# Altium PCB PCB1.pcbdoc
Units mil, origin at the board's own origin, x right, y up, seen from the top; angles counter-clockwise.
Board outline 4950 x 4950 mil, 2 copper layers (Top Layer, Bottom Layer); 35 components, 39 nets, 176 pads, 65 vias.
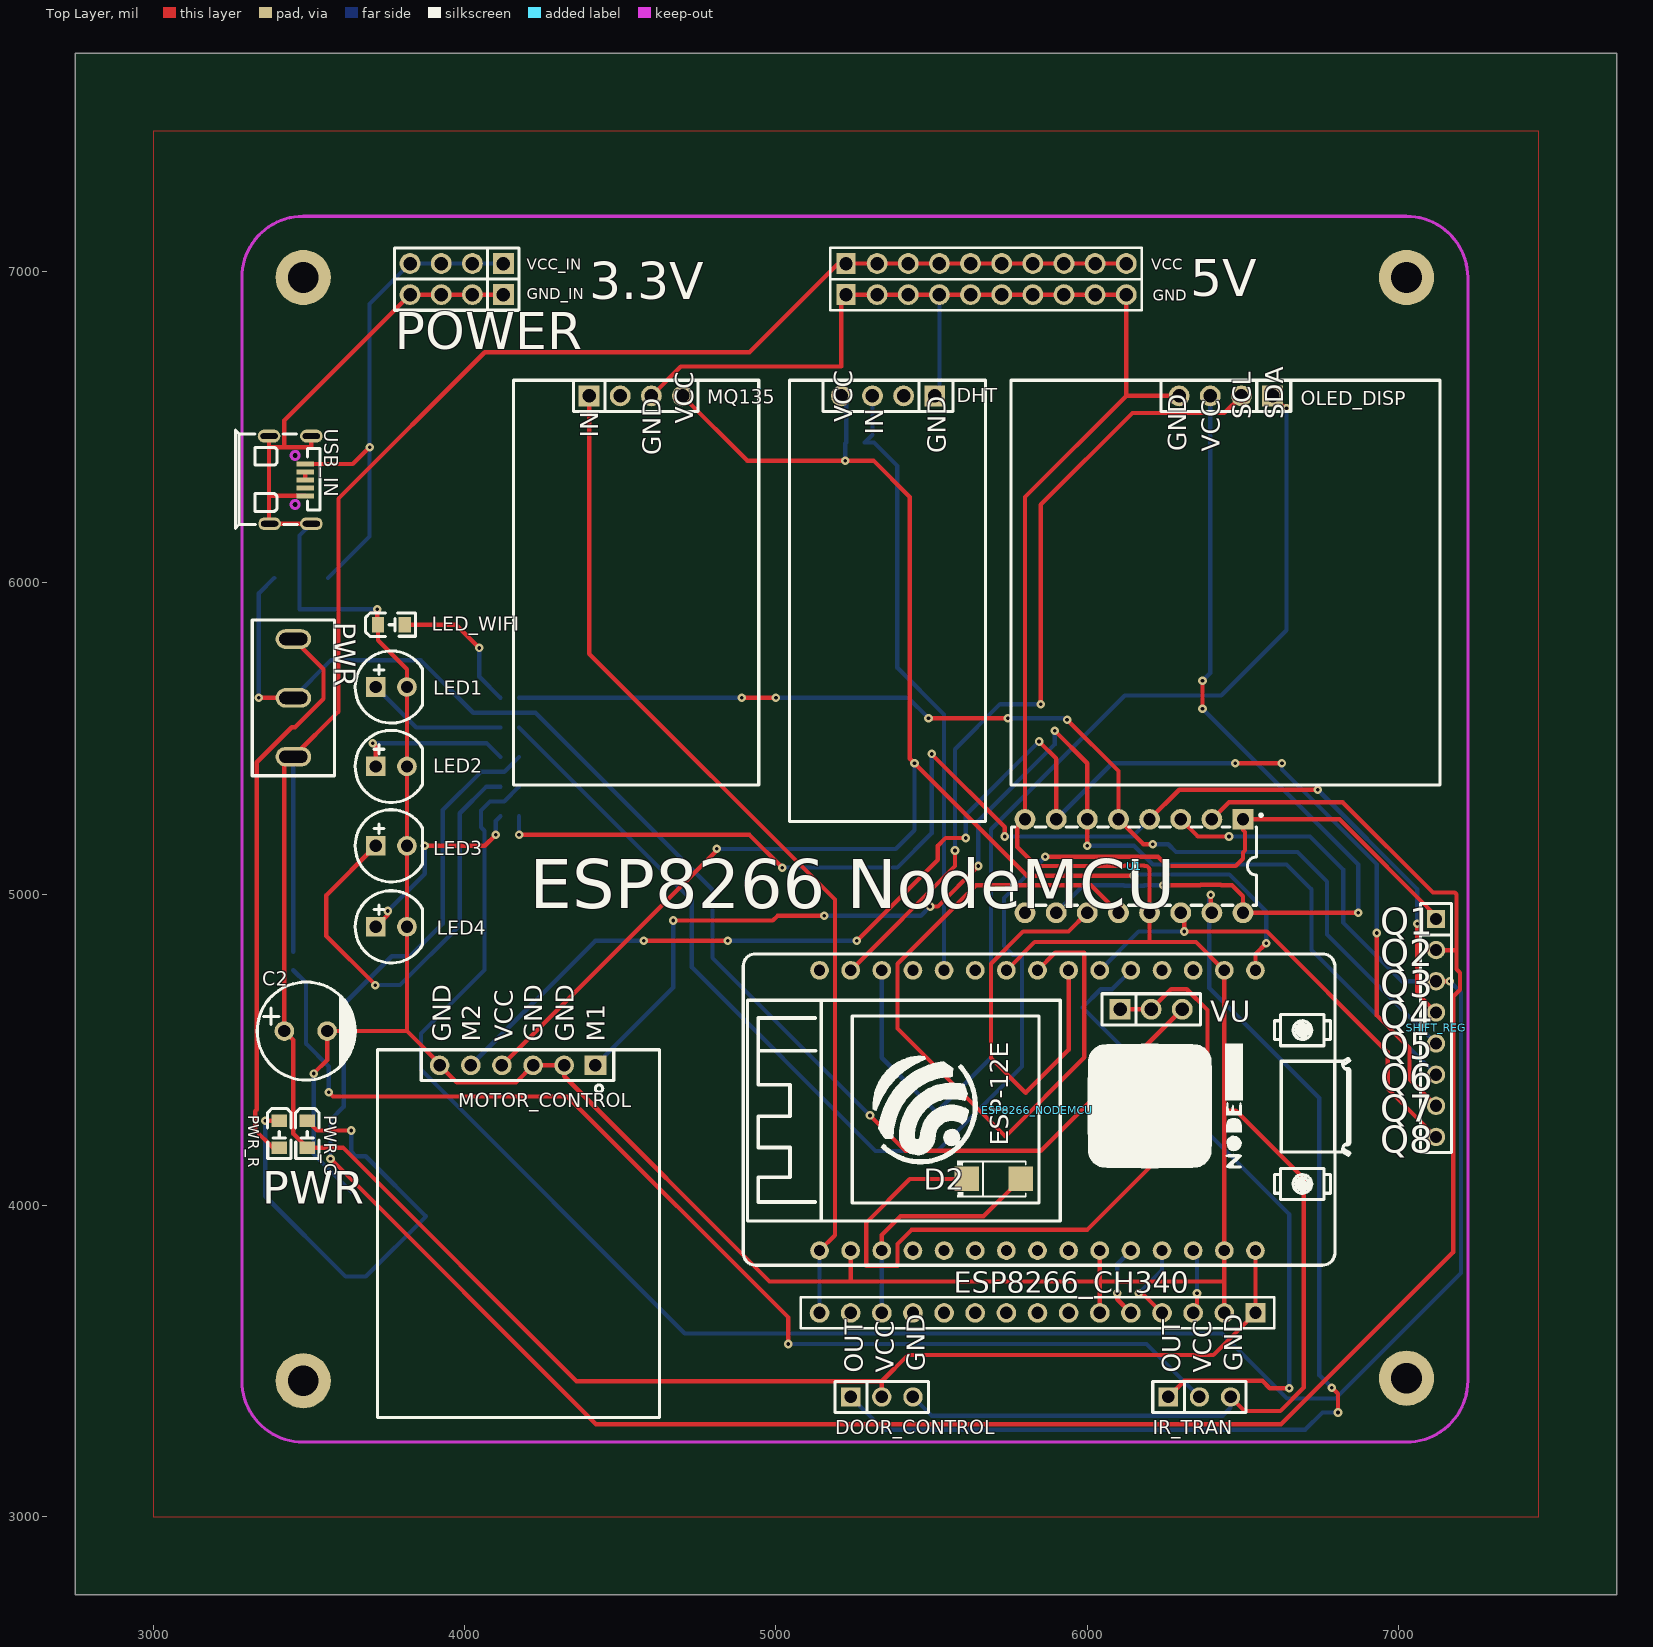
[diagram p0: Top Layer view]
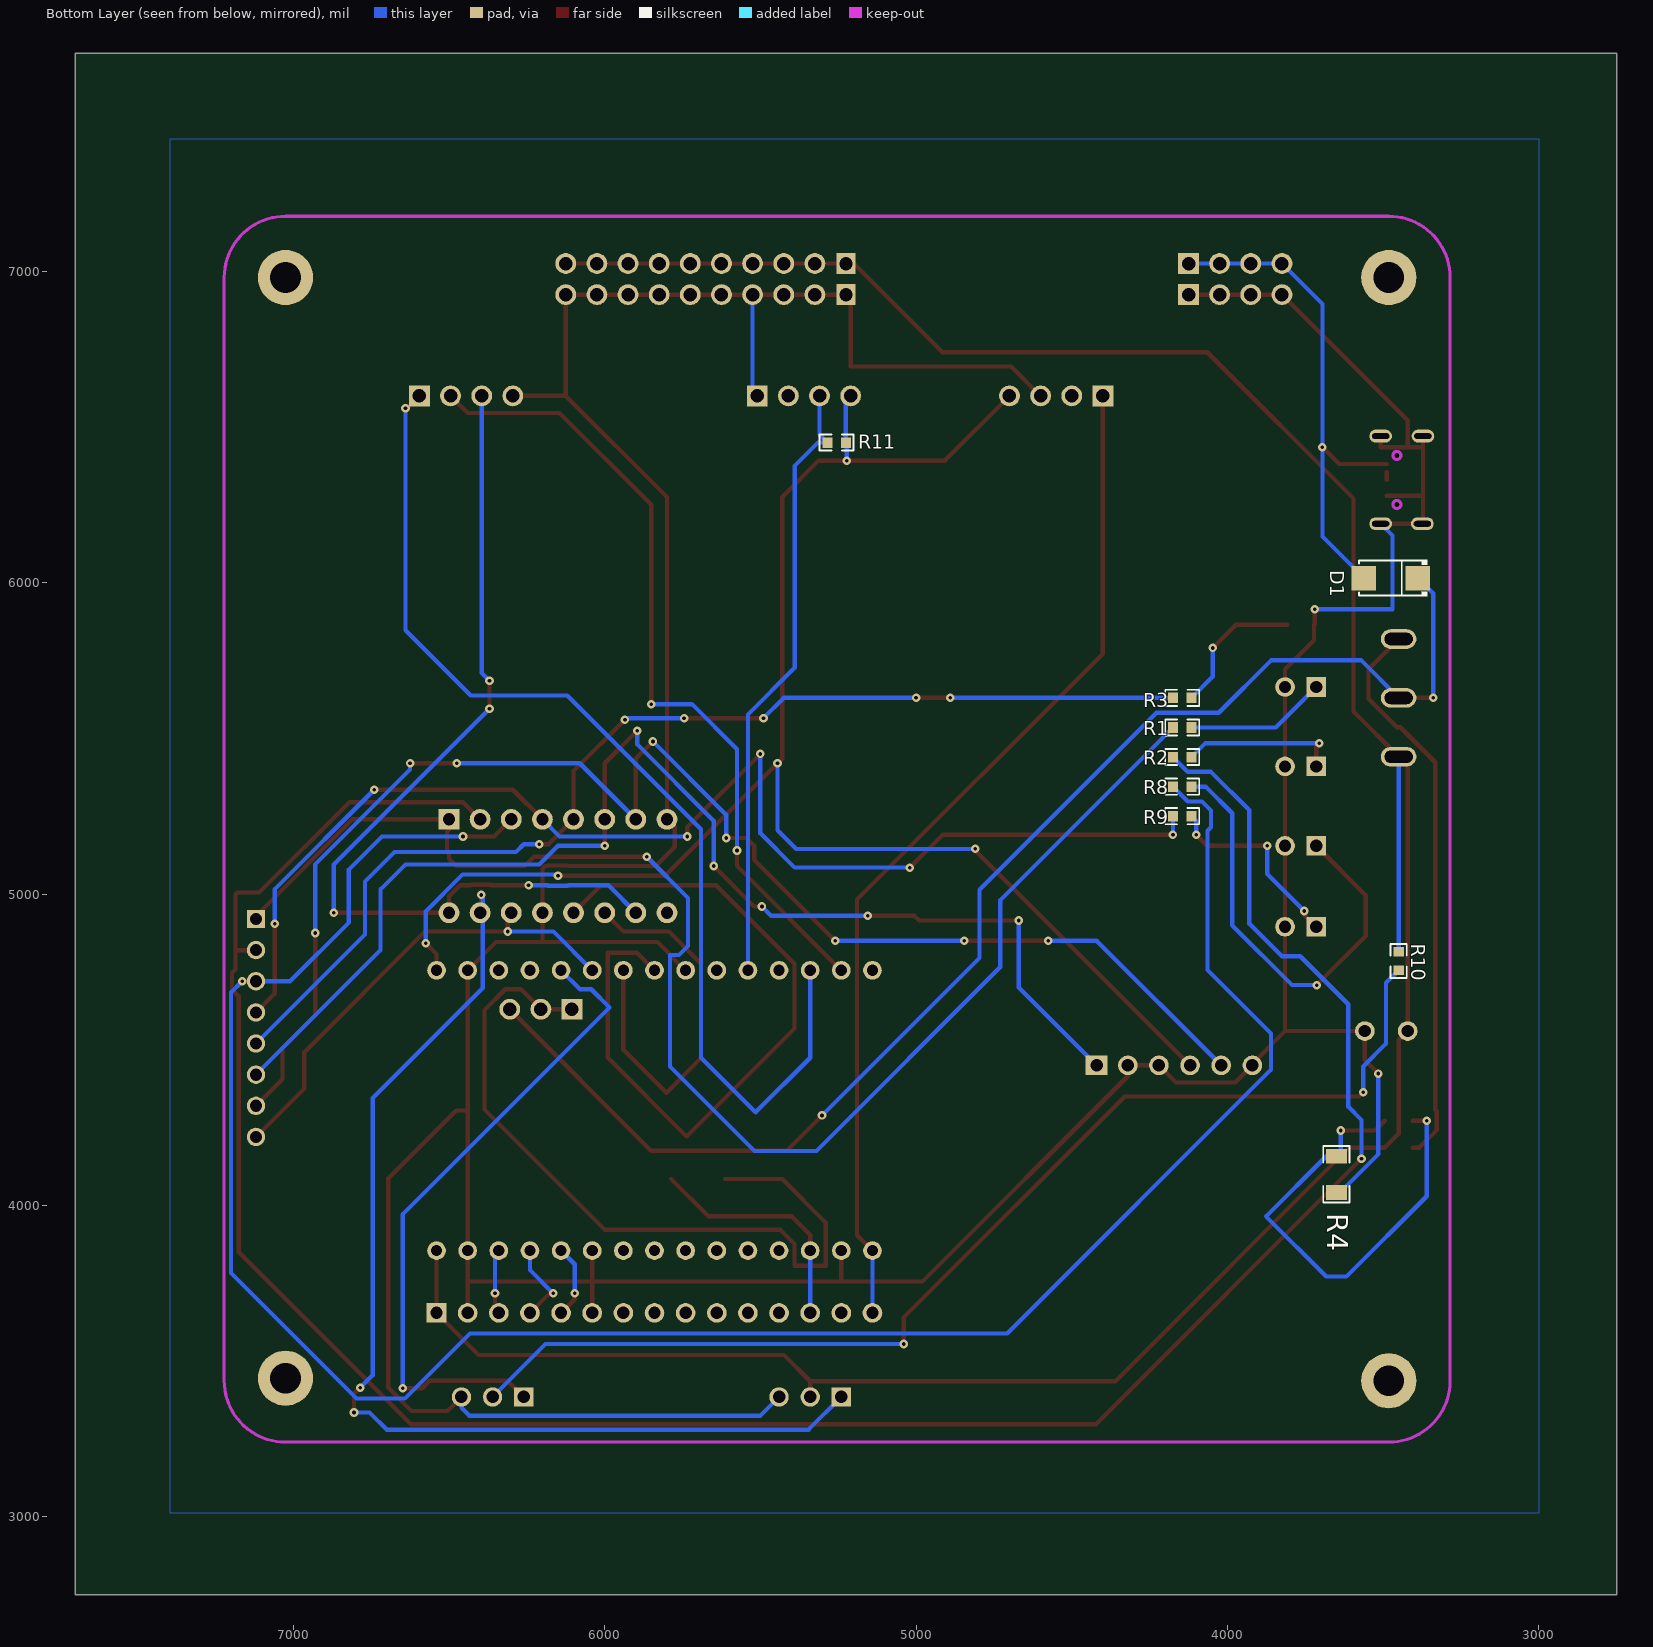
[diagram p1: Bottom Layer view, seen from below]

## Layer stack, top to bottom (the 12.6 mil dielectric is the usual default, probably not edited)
Top Layer: signal copper (thickness not stored)
Dielectric: dielectric 12.6, FR-4, Dk 4.8
Bottom Layer: signal copper (thickness not stored)

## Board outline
7700,2750 2750,2750 2750,7700 7700,7700

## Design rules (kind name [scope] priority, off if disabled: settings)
Clearance Default [All] p1: gap=7 ignorepadtopadclearanceinfootprint=FALSE except(0: Region-Region Region-Text Text-Text; 6: Track-Track Track-SMDPad SMDPad-SMDPad Track-THPad SMDPad-THPad THPad-THPad Track-Via SMDPad-Via THPad-Via Via-Via Track-Fill SMDPad-Fill THPad-Fill Via-Fill Fill-Fill Track-Region SMDPad-Region THPad-Region Via-Region Fill-Region Track-Poly SMDPad-Poly THPad-Poly Via-Poly Fill-Poly Region-Poly Poly-Poly Track-Text SMDPad-Text THPad-Text Via-Text Fill-Text Poly-Text Track-Sheet SMDPad-Sheet THPad-Sheet Via-Sheet Fill-Sheet Region-Sheet Poly-Sheet Text-Sheet Track-Hole SMDPad-Hole THPad-Hole Via-Hole Fill-Hole Region-Hole Poly-Hole Text-Hole Sheet-Hole)
Clearance Power [All] p1: gap=7 ignorepadtopadclearanceinfootprint=FALSE except(0: Region-Region Region-Text Text-Text; 6: Track-Sheet SMDPad-Sheet THPad-Sheet Via-Sheet Fill-Sheet Region-Sheet Poly-Sheet Text-Sheet Sheet-Hole; 6.3: Track-Track Track-SMDPad SMDPad-SMDPad Track-THPad SMDPad-THPad THPad-THPad Track-Via SMDPad-Via THPad-Via Via-Via Track-Fill SMDPad-Fill THPad-Fill Via-Fill Fill-Fill Track-Region SMDPad-Region THPad-Region Via-Region Fill-Region Track-Poly SMDPad-Poly THPad-Poly Via-Poly Fill-Poly Region-Poly Poly-Poly Track-Text SMDPad-Text THPad-Text Via-Text Fill-Text Poly-Text Track-Hole SMDPad-Hole THPad-Hole Via-Hole Fill-Hole Region-Hole Poly-Hole Text-Hole)
Clearance Wide [All] p1: gap=7 ignorepadtopadclearanceinfootprint=FALSE except(0: Region-Region Region-Text Text-Text; 6: Track-Sheet SMDPad-Sheet THPad-Sheet Via-Sheet Fill-Sheet Region-Sheet Poly-Sheet Text-Sheet Sheet-Hole; 7.1: Track-Track Track-SMDPad SMDPad-SMDPad Track-THPad SMDPad-THPad THPad-THPad Track-Via SMDPad-Via THPad-Via Via-Via Track-Fill SMDPad-Fill THPad-Fill Via-Fill Fill-Fill Track-Region SMDPad-Region THPad-Region Via-Region Fill-Region Track-Poly SMDPad-Poly THPad-Poly Via-Poly Fill-Poly Region-Poly Poly-Poly Track-Text SMDPad-Text THPad-Text Via-Text Fill-Text Poly-Text Track-Hole SMDPad-Hole THPad-Hole Via-Hole Fill-Hole Region-Hole Poly-Hole Text-Hole)
DiffPairsRouting differentialPair [All] p1: maxuncoupledlength=10 minlimit=6 maxlimit=50 mostfreqgap=6 toplayer_minwidth=5 toplayer_prefwidth=10 toplayer_maxwidth=100 bottomlayer_minwidth=5 bottomlayer_prefwidth=10 bottomlayer_maxwidth=100
PasteMaskExpansion Common [All] p1:
PlaneConnect Default [All] p1: planeconnectstyle=Relief reliefexpansion=20 reliefentries=4 reliefconductorwidth=0 reliefairgap=10
PlaneConnect Power [All] p1: planeconnectstyle=Relief reliefexpansion=20 reliefentries=4 reliefconductorwidth=0 reliefairgap=10
PlaneConnect Wide [All] p1: planeconnectstyle=Relief reliefexpansion=20 reliefentries=4 reliefconductorwidth=0 reliefairgap=10
PolygonConnect gge880165 [All] p1: connectstyle=Relief reliefentries=4 polygonreliefangle="90 Angle" airgapwidth=10
PolygonConnect gge880153 [All] p1: connectstyle=Relief reliefentries=4 polygonreliefangle="90 Angle" airgapwidth=10
RoutingVias Default [All] p1: viastyle="Through Hole" holewidth=11.8 minholewidth=11.8 maxholewidth=2362 width=27.6 minwidth=27.6 maxwidth=3938
RoutingVias Power [All] p1: viastyle="Through Hole" holewidth=11.8 minholewidth=11.8 maxholewidth=2362 width=27.6 minwidth=27.6 maxwidth=3938
RoutingVias Wide [All] p1: viastyle="Through Hole" holewidth=11.8 minholewidth=11.8 maxholewidth=2362 width=47.2 minwidth=47.2 maxwidth=3938
SolderMaskExpansion Common [All] p1: useseparateexpansions=TRUE expansion=2 expansionbottom=2
Width Default [All] p1: maxlimit=1000 minlimit=14 preferedwidth=14
Width Power [All] p1: maxlimit=1000 minlimit=20 preferedwidth=20
Width Wide [All] p1: maxlimit=1000 minlimit=39 preferedwidth=39

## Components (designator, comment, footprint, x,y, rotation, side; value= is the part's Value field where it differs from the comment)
C2 "1000uF" CAP-TH_BD8.0-P3.50-D0.6-FD 3490,4560 r0 top
D1 "SS34-A" SMA_L4.3-W2.6-LS5.2-RD 3475,6015 r0 bottom
D2 "SS34-A" SMA_L4.3-W2.6-LS5.2-RD 5700,4085 r0 top
DHT "HDR-F_2.54_1x4P" HDR-TH_4P-P2.54-V-F 5360,6600 r180 top
DOOR_CONTROL "HDR-F_2.54_1x3P" HDR-TH_3P-P2.54-V-F 5340,3385 r0 top
ESP8266_CH340 "HDR-F_2.54_1x15P" HDR-TH_15P-P2.54-V-F-1 5840,3655 r180 top
ESP8266_NODEMCU "NodeMCU8266" NODEMCU8266 6540,3855 r90 top
GND "HDR-M_2.54_1x10P" HDR-TH_10P-P2.54-V-M-1 5675,6925 r0 top
GND_IN "HDR-M_2.54_1x4P" HDR-TH_4P-P2.54-V-M 3975,6925 r180 top
IR_TRAN "HDR-F_2.54_1x3P" HDR-TH_3P-P2.54-V-F 6360,3385 r0 top
LED1 "LTST-C171KFKT" LED-TH_BD5.8-P2.54-RD 3765,5665 r0 top
LED2 "LTST-C171KFKT" LED-TH_BD5.8-P2.54-RD 3765,5410 r0 top
LED3 "LTST-C171KFKT" LED-TH_BD5.8-P2.54-RD 3765,5155 r0 top
LED4 "LTST-C171KFKT" LED-TH_BD5.8-P2.54-RD 3765,4895 r0 top
LED_WIFI "LTST-C171KFKT" LED0805-RD_ORANGE 3765,5865 r0 top
MOTOR_CONTROL "HDR-F_2.54_1x6P" HDR-TH_6P-P2.54-V-F 4170,4450 r180 top
MQ135 "HDR-M_2.54_1x4P" HDR-TH_4P-P2.54-V-M 4550,6600 r0 top
OLED_DISP "HDR-F_2.54_1x4P" HDR-TH_4P-P2.54-V-F 6445,6600 r180 top
PWR "SS12D10G5" SS12D10G5 3450,5630 r270 top
PWR_G "LTST-C170GKT" LED0805-RD_GREEN 3495,4228.94 r270 top
PWR_R "HL-PSC-2012S9AC-CZ" LED0805-RD_RED 3405,4228.94 r270 top
R1 "Res_0603" R0603 4145,5535 r180 bottom
R2 "Res_0603" R0603 4145,5440 r180 bottom
R3 "Res_0603" R0603 4145,5630 r180 bottom
R4 "10K" R1206 3650,4100 r90 bottom
R8 "Res_0603" R0603 4145,5345 r180 bottom
R9 "Res_0603" R0603 4145,5250 r180 bottom
R10 "Res_0603" R0603 3450,4785 r270 bottom
R11 "Res_0603" R0603 5255,6450 r0 bottom
SHIFT_REG "HDR-M_2.54_1x8P" HDR-TH_8P-P2.54-V-M 7120,4570 r270 top
U1 "74HC595D,118" CDIP-16_L19.7-W6.6-P2.54-LS7.6-BL 6150,5090 r180 top
USB_IN "MICROUSB_5PIN_4DIP" MICRO-USB-SMD_U254-051N-4BH806 3440,6330 r270 top
VCC "HDR-M_2.54_1x10P" HDR-TH_10P-P2.54-V-M-1 5675,7025 r0 top
VCC_IN "HDR-M_2.54_1x4P" HDR-TH_4P-P2.54-V-M 3975,7025 r180 top
VU "HDR-M_2.54_1x3P" HDR-TH_3P-P2.54-V-M 6205,4630 r0 top

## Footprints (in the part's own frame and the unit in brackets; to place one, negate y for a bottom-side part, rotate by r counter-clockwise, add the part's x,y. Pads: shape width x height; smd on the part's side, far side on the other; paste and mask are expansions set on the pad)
CAP-TH_BD8.0-P3.50-D0.6-FD [mm]
  round 1.6 hole 1: 1(-1.75,0) 2(1.75,0)
  silkscreen extent -3.96,-4 4.04,4
CDIP-16_L19.7-W6.6-P2.54-LS7.6-BL [mm]
  rect 1.7x1.7 hole 1: 1(-8.89,-3.81)
  round 1.7 hole 1: 2(-6.35,-3.81) 3(-3.81,-3.81) 4(-1.27,-3.81) 5(1.27,-3.81) 6(3.81,-3.81) 7(6.35,-3.81) 8(8.89,-3.81) 9(8.89,3.81) 10(6.35,3.81) 11(3.81,3.81) 12(1.27,3.81) 13(-1.27,3.81) 14(-3.81,3.81) 15(-6.35,3.81) 16(-8.89,3.81)
  silkscreen extent -10.46,-4.26 10,3.2
HDR-TH_3P-P2.54-V-F [mil]
  rect 62x62 hole 40.16: 1(-100,0)
  round 62 hole 40.16: 2(0,0) 3(100,0)
  silkscreen extent -150,-50 150,50
HDR-TH_3P-P2.54-V-M [mm]
  rect 1.7x1.7 hole 1.1: 1(-2.54,0)
  round 1.7 hole 1.1: 2(0,0) 3(2.54,0)
  silkscreen extent -4.02,-1.27 4.02,1.27
HDR-TH_4P-P2.54-V-F [mm]
  rect 1.7x1.7 hole 1.1: 1(-3.81,0)
  round 1.7 hole 1.1: 2(-1.27,0) 3(1.27,0) 4(3.81,0)
  silkscreen extent -5.29,-1.27 5.29,1.27
HDR-TH_4P-P2.54-V-M [mm]
  rect 1.7x1.7 hole 1.1: 1(-3.81,0)
  round 1.7 hole 1.1: 2(-1.27,0) 3(1.27,0) 4(3.81,0)
  silkscreen extent -5.08,-1.27 5.08,1.27
HDR-TH_6P-P2.54-V-F [mm]
  rect 1.8x1.6 hole 1.02: 1(-6.35,0)
  round 1.6 hole 1.02: 2(-3.81,0) 3(-1.27,0) 4(1.27,0) 5(3.81,0) 6(6.35,0)
  silkscreen extent -7.85,-1.25 7.85,2.2
HDR-TH_8P-P2.54-V-M [mm]
  rect 1.5x1.5 hole 1: 1(-8.89,0)
  round 1.5 hole 1: 2(-6.35,0) 3(-3.81,0) 4(-1.27,0) 5(1.27,0) 6(3.81,0) 7(6.35,0) 8(8.89,0)
  silkscreen extent -10.16,-1.27 10.16,1.27
HDR-TH_10P-P2.54-V-M-1 [mm]
  rect 1.575x1.7 hole 1.1: 1(-11.43,0)
  round 1.7 hole 1.1: 2(-8.89,0) 3(-6.35,0) 4(-3.81,0) 5(-1.27,0) 6(1.27,0) 7(3.81,0) 8(6.35,0) 9(8.89,0) 10(11.43,0)
  silkscreen extent -12.7,-1.27 12.7,1.27
HDR-TH_15P-P2.54-V-F-1 [mm]
  rect 1.6x1.575 hole 1: 1(-17.78,0)
  round 1.6 hole 1: 2(-15.24,0) 3(-12.7,0) 4(-10.16,0) 5(-7.62,0) 6(-5.08,0) 7(-2.54,0) 8(0,0) 9(2.54,0) 10(5.08,0) 11(7.62,0) 12(10.16,0) 13(12.7,0) 14(15.24,0) 15(17.78,0)
  silkscreen extent -19.3,-1.27 19.3,1.27
LED0805-RD_GREEN [mm]
  rect 1x1.25 smd: 1(-1.1,0) 2(1.1,0)
  silkscreen extent -2.1,-0.95 1.98,0.96
LED0805-RD_ORANGE [mm]
  rect 1x1.25 smd: 1(-1.1,0) 2(1.1,0)
  silkscreen extent -2.1,-0.95 1.98,0.96
LED0805-RD_RED [mm]
  rect 1x1.25 smd: 1(-1.1,0) 2(1.1,0)
  silkscreen extent -2.1,-0.95 1.98,0.96
LED-TH_BD5.8-P2.54-RD [mm]
  round 1.6 hole 1: 1(1.27,0)
  rect 1.6x1.6 hole 1: 2(-1.27,0)
  silkscreen extent -2.96,-2.95 2.54,2.94
MICRO-USB-SMD_U254-051N-4BH806 [mm]
  rect 0.4x1.4 smd: 1(-1.3,1.225) 2(-0.65,1.225) 3(0,1.225) 4(0.65,1.225) 5(1.3,1.225)
  oval 1.05x1.85 hole 0.45 slot 1.4 at 90 deg: 6(-3.575,1.725) 7(-3.575,-1.725) 8(3.575,1.725) 9(3.575,-1.675)
  Multi-Layer board cut-out: -2,0.73 -2.16,0.684 -2.276,0.566 -2.319,0.405 -2.276,0.244 -2.16,0.126 -2,0.08 -2,0.08 -1.84,0.126 -1.724,0.244 -1.681,0.405 -1.724,0.566 -1.84,0.684 -2,0.73
  Multi-Layer board cut-out: 2,0.73 1.84,0.684 1.724,0.566 1.681,0.405 1.724,0.244 1.84,0.126 2,0.08 2,0.08 2.16,0.126 2.276,0.244 2.319,0.405 2.276,0.566 2.16,0.684 2,0.73
  Multi-Layer keep-out circle w0.254: c-2,0.405 r0.325
  Multi-Layer keep-out circle w0.254: c2,0.405 r0.325
  silkscreen extent -4.06,-4.48 3.94,2.42
NODEMCU8266 [mil]
  round 60 hole 36: 1(0,0) 2(0,100) 3(0,200) 4(0,300) 5(0,400) 6(0,500) 7(0,600) 8(0,700) 9(0,800) 10(0,900) 11(0,1000) 12(0,1100) 13(0,1200) 14(0,1300) 15(0,1400) 16(900,0) 17(900,100) 18(900,200) 19(900,300) 20(900,400) 21(900,500) 22(900,600) 23(900,700) 24(900,800) 25(900,900) 26(900,1000) 27(900,1100) 28(900,1200) 29(900,1300) 30(900,1400)
  silkscreen extent -47,-303 953,1645
R0603 [mil]
  rect 31.75x34.02 smd: 1(-29.66,0) 2(29.66,0)
  silkscreen extent -55,-26 55,26
R1206 [mil]
  rect 47.54x66.97 smd: 1(-58.22,0) 2(58.22,0)
  silkscreen extent -91,-42 91,42
SMA_L4.3-W2.6-LS5.2-RD [mm]
  rect 2x2 smd: 1(-2.2,0) 2(2.2,0)
  silkscreen extent -2.98,-1.5 2.6,1.5
SS12D10G5 [mm]
  oval 1.6x2.9 hole 1 slot 2.3 at 90 deg: 1(-4.8,0) 2(0,0) 3(4.8,0)
  silkscreen extent -6.35,-3.35 6.35,3.35

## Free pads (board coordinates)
  round 177.17 hole 98.43: 31(3481.85,3436.85) 31(3481.85,6980.16) 31(7025.16,3445) 31(7025.16,6980.16)

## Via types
v1: diameter 27.6, hole 11.8, Top Layer to Bottom Layer, 65 vias

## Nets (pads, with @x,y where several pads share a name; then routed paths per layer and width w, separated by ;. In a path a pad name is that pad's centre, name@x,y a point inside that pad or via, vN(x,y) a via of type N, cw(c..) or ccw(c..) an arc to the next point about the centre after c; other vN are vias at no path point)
3V3: DHT.4 ESP8266_NODEMCU.16 MOTOR_CONTROL.4 MQ135.4 R11.1 | length 5330.3
  Top Layer w13.8: MOTOR_CONTROL.4 4810,5140 v1(4810,5145) ; MQ135.4 4908.01,6391.99 v1(5222.57,6391.99) 5313.01,6391.99 5430,6275 5430,5435 v1(5445,5420) 5805.92,5059.08 v1(6150,5059.08) ; ESP8266_NODEMCU.16 6540,4807 v1(6574.94,4841.94)
  Bottom Layer w13.8: v1(4810,5145) 5385,5145 5445,5205 v1(5445,5420) ; DHT.4 5225.34,6584.66 R11.1 5222.57,6447.23 v1(5222.57,6391.99) ; v1(6150,5059.08) 6153.45,5062.53 6456.15,5062.53 6574.94,4943.75 v1(6574.94,4841.94)
$1N1204: LED1.2 R1.2 | length 454.2
  Bottom Layer w13.8: LED1.2 3845,5535 R1.2
$1N1211: LED2.2 R2.2 | length 507.9
  Top Layer w13.8: v1(3704.95,5484.8) 3715,5474.75 LED2.2
  Bottom Layer w13.8: v1(3704.95,5484.8) 4070.54,5484.8 R2.2
$1N2250: LED_WIFI.2 R3.2 | length 458.4
  Top Layer w13.8: LED_WIFI.2 3972.61,5865 v1(4047.11,5790.5)
  Bottom Layer w13.8: v1(4047.11,5790.5) 4047.11,5698.23 R3.2
$1N4146: USB_IN.2 USB_IN.3 | length 25.6
  Top Layer w13.8: USB_IN.3 USB_IN.2
$1N8496: PWR_G.1 PWR_R.1 R4.2 | length 1539.2
  Top Layer w13.8: v1(3360,4272.25) PWR_R.1 ; PWR_G.1 3526.53,4240.73 v1(3635.85,4240.73)
  Bottom Layer w13.8: v1(3360,4272.25) 3360,4029.67 3618.07,3771.6 3682.83,3771.6 3876.14,3964.91 3682.83,4158.22 R4.2 3635.85,4172.37 v1(3635.85,4240.73)
$1N8506: PWR.1 PWR_R.2 | length 1815.4
  Top Layer w13.8: PWR_R.2 3383.92,4185.63 3327.3,4242.25 3327.3,4302.25 3332.7,4307.65 3332.7,5423.51 3444.7,5535.51 3455.3,5535.51 3547.15,5627.36 3547.15,5721.83 PWR.1
$1N8906: D2.1 VU.1 VU.2 | length 2519.8
  Top Layer w13.8: D2.1 5430.01,4085 5290.44,3945.43 5290.44,3805.86 5390.44,3805.86 5390.44,3876.35 5435.63,3921.54 5999.44,3921.54 6385.78,4307.88 6385.78,4627.9 6319.47,4694.22 6269.22,4694.22 VU.2 VU.1
$1N16524: LED3.2 R8.2 | length 1455.3
  Top Layer w13.8: v1(3713.62,4707.62) 3555.75,4865.49 3555.75,4995.75 LED3.2
  Bottom Layer w13.8: v1(3713.62,4707.62) 3792.62,4707.62 3984.51,4899.51 3984.51,5259.51 4070,5345 R8.2
$1N16573: LED4.2 R9.2 | length 633.7
  Top Layer w13.8: LED4.2 3753.16,4933.16 v1(3753.16,4945.63) ; v1(3872.3,5155) 4065,5155 v1(4100,5190)
  Bottom Layer w13.8: v1(3753.16,4945.63) 3872.3,5064.76 v1(3872.3,5155) ; v1(4100,5190) 4100,5234.66 R9.2
$1N18615: ESP8266_CH340.3 ESP8266_NODEMCU.3 | length 210.2
  Top Layer w13.8: ESP8266_CH340.3 6352.3,3667.3 v1(6352.3,3717.55)
  Bottom Layer w13.8: ESP8266_NODEMCU.3 6352.3,3842.7 v1(6352.3,3717.55)
$1N18620: ESP8266_CH340.4 ESP8266_NODEMCU.4 | length 269.1
  Top Layer w13.8: v1(6165.2,3717.55) 6177.45,3717.55 ESP8266_CH340.4
  Bottom Layer w13.8: v1(6165.2,3717.55) 6240,3792.36 ESP8266_NODEMCU.4
$1N18625: ESP8266_CH340.5 ESP8266_NODEMCU.5 | length 236.3
  Top Layer w13.8: v1(6096.15,3717.55) 6096.15,3698.85 ESP8266_CH340.5
  Bottom Layer w13.8: v1(6096.15,3717.55) 6096.15,3811.15 ESP8266_NODEMCU.5
$1N24040: IR_TRAN.2 R10.2 | length 3690.1
  Top Layer w13.8: v1(3563.72,4363.93) 3577.65,4350 4330,4350 5040,3640 v1(5040,3555)
  Bottom Layer w13.8: R10.2 3490.46,4714.88 3490.46,4519.63 3563.72,4446.37 v1(3563.72,4363.93) ; v1(5040,3555) 6190,3555 IR_TRAN.2
$1N25553: D2.2 ESP8266_CH340.13 ESP8266_NODEMCU.13 | length 771.2
  Top Layer w13.8: ESP8266_NODEMCU.13 5340,3905 5400.21,3965.21 5666.82,3965.21 D2.2
  Bottom Layer w13.8: ESP8266_CH340.13 ESP8266_NODEMCU.13
CLK_PIN: ESP8266_NODEMCU.22 U1.11 | length 1288.2
  Top Layer w13.8: ESP8266_NODEMCU.22 5940,4500 5801.94,4361.94 5690.44,4473.44 5690.44,4776.35 5793.82,4879.73 5939.73,4879.73 U1.11
D0_PIN: ESP8266_NODEMCU.30
DATA_PIN: ESP8266_NODEMCU.21 SHIFT_REG.8 U1.14 | length 1538.2
  Top Layer w13.8: U1.14 6311.51,4928.49 v1(6311.51,4879.73) 6576.74,4879.73 6964.45,4492.02 6964.45,4375.55 SHIFT_REG.8
  Bottom Layer w13.8: ESP8266_NODEMCU.21 6164.73,4879.73 v1(6311.51,4879.73)
DHT_PIN: DHT.3 ESP8266_NODEMCU.26 R11.2 | length 1978.8
  Bottom Layer w13.8: DHT.3 5310,6475.34 R11.2 5314.66,6450 5390,6374.66 5390,5726.56 5540,5576.56 ESP8266_NODEMCU.26
DOOR_PIN: DOOR_CONTROL.1 U1.15 | length 3525.5
  Top Layer w13.8: v1(6396.41,4997.24) 6396.41,4943.59 U1.15 ; v1(6785,3415) 6805,3395 v1(6805,3335)
  Bottom Layer w13.8: DOOR_CONTROL.1 5345,3280 6700,3280 6755,3335 v1(6805,3335) ; v1(6396.41,4997.24) 6391.51,4992.34 6391.51,4698.49 6745,4345 6745,3455 v1(6785,3415)
GND: 
IR_TRAN_PIN: ESP8266_NODEMCU.20 IR_TRAN.1 | length 2121.9
  Top Layer w13.8: IR_TRAN.1 6311.68,3436.68 6562.37,3436.68 6586.01,3413.03 v1(6648.19,3413.03)
  Bottom Layer w13.8: ESP8266_NODEMCU.20 6079.34,4694.34 6043.06,4694.34 5984.48,4635.76 6648.19,3972.04 v1(6648.19,3413.03)
LATCH_PIN: ESP8266_NODEMCU.23 U1.12 | length 2417.6
  Top Layer w13.8: ESP8266_NODEMCU.23 5896.83,4811.83 5990.44,4811.83 5990.44,4475.44 5736.74,4221.74 5390.44,4568.05 5390.44,4776.35 5642.25,5028.16 6011.84,5028.16 U1.12
MOTOR_1: MOTOR_CONTROL.1 SHIFT_REG.6 U1.6 | length 4109.7
  Top Layer w13.8: v1(4670,4915) 4990,4915 5005,4930 v1(5155,4930) ; v1(5495,4960) 5520,4960 v1(5650,5090) ; v1(5895,5525) 6000,5420 U1.6 v1(6000,5155)
  Bottom Layer w13.8: MOTOR_CONTROL.1 4670,4700 v1(4670,4915) ; v1(5155,4930) 5465,4930 v1(5495,4960) ; v1(5650,5090) 5650,5235 5895,5480 v1(5895,5525) ; v1(6000,5155) 6150,5155 6210,5095 6640,5095 6720,5015 6720,4820 SHIFT_REG.6
MOTOR_2: MOTOR_CONTROL.5 SHIFT_REG.7 U1.7 | length 4703.5
  Top Layer w13.8: v1(4575,4850) v1(4845,4850) ; v1(5260,4850) 5520,5110 5520,5155 5545,5180 v1(5610,5180) ; v1(5845,5490) 5900,5435 U1.7 ; v1(6475,5420) v1(6625,5420) ; v1(6930,4875) 6930,4610 7035,4505 7035,4405 SHIFT_REG.7
  Bottom Layer w13.8: MOTOR_CONTROL.5 4420,4850 v1(4575,4850) ; v1(4845,4850) v1(5260,4850) ; v1(5610,5180) 5610,5255 v1(5845,5490) ; U1.7 6080,5420 v1(6475,5420) ; v1(6625,5420) 6625,5400 6930,5095 v1(6930,4875)
MQ_PIN: ESP8266_CH340.15 ESP8266_NODEMCU.15 MQ135.1 | length 3292.4
  Top Layer w13.8: MQ135.1 4400,5771.82 5189.36,4982.46 5189.36,3904.36 ESP8266_NODEMCU.15
  Bottom Layer w13.8: ESP8266_CH340.15 ESP8266_NODEMCU.15
Q1: R1.1 SHIFT_REG.1 U1.1 | length 4734.3
  Top Layer w13.8: v1(5865,5120) 6227.18,5120 6257.18,5090 6476.48,5090 6500,5113.52 6500,5133.78 6506.52,5140.3 6506.52,5199.18 6500,5205.7 U1.1 6810,5240 7120,4930 SHIFT_REG.1
  Bottom Layer w13.8: R1.1 4730,4979.66 4730,4765 5320,4175 5519.14,4175 5790.44,4446.29 5790.44,4804.14 5761.43,4804.14 5732.42,4833.15 5732.42,4987.42 v1(5865,5120)
Q2: R2.1 SHIFT_REG.2 U1.2 | length 7966.1
  Top Layer w13.8: v1(3569.31,4150.36) 4422.32,3297.34 6622.34,3297.34 7175,3850 7175,4670.97 7196.9,4692.87 7196.9,4747.13 7185.76,4758.27 7185.76,4820 ; U1.2 6455,5295 6820,5295 7110,5005 7180,5005 7185.76,4999.24 7185.76,4820 ; SHIFT_REG.2 7185.76,4820
  Bottom Layer w13.8: v1(3569.31,4150.36) 3569.31,4274.36 3612.24,4317.29 3612.24,4645.84 3766.4,4800 3825,4800 3930,4905 3930,5270 4052.5,5392.5 4127.16,5392.5 R2.1
Q3: R8.1 SHIFT_REG.3 U1.3 | length 7150.8
  Top Layer w13.8: U1.3 6355,5185 v1(6455,5185) ; SHIFT_REG.3 v1(7164.2,4720)
  Bottom Layer w13.8: R8.1 4127.16,5297.5 4081.56,5297.5 4052.5,5268.43 4052.5,5214.56 4064.03,5203.03 4064.03,4756.24 3860,4552.21 3860,4436.15 4707.33,3588.82 6432.81,3588.82 6641.75,3379.87 6796.87,3379.87 7200,3783 7200,4684.2 v1(7164.2,4720) ; v1(6455,5185) 6715.06,5185 6821.5,5078.56 6821.5,4908.88 7010.38,4720 SHIFT_REG.3
Q4: R9.1 SHIFT_REG.4 U1.4 | length 4031.1
  Top Layer w13.8: v1(4175,5190) 4915,5190 v1(5020,5085) ; v1(5500,5450) 5735,5215 v1(5735,5185) ; U1.4 6295,5335 v1(6740,5335) ; v1(7060,4905) 7060,4680 SHIFT_REG.4
  Bottom Layer w13.8: R9.1 4174.66,5190.34 v1(4175,5190) ; v1(5020,5085) 5390,5085 5500,5195 v1(5500,5450) ; v1(5735,5185) 6145,5185 U1.4 ; v1(6740,5335) 7060,5015 v1(7060,4905)
RX_PIN: ESP8266_NODEMCU.19
SCL_PIN: ESP8266_NODEMCU.29 OLED_DISP.2 | length 2613.8
  Top Layer w13.8: ESP8266_NODEMCU.29 5575,5090 v1(5575,5140) ; v1(5850,5610) 5850,6250 6145,6545 6440,6545 OLED_DISP.2
  Bottom Layer w13.8: v1(5575,5140) 5575,5465 5720,5610 v1(5850,5610)
SDA_PIN: ESP8266_NODEMCU.28 OLED_DISP.1 | length 3498.6
  Top Layer w13.8: OLED_DISP.1 6634.34,6560.66 v1(6639.73,6560.66)
  Bottom Layer w13.8: ESP8266_NODEMCU.28 5340,4474.23 5515.22,4299.01 5690.44,4474.23 5690.44,5208.15 6119.93,5637.65 6429.85,5637.65 6639.73,5847.53 v1(6639.73,6560.66)
TX_PIN: ESP8266_NODEMCU.18
VCC: OLED_DISP.3 U1.10 U1.16 | length 2954.3
  Top Layer w13.8: v1(6244.45,5028.16) 6362.82,5028.16 6364.6,5029.94 6428.22,5029.94 6430,5028.16 6464.55,5028.16 6500,4992.71 U1.16 v1(6870,4940) ; v1(6370,5595) v1(6370,5685)
  Bottom Layer w13.8: U1.10 5988.16,5028.16 6116.41,5028.16 6118.19,5026.38 6181.81,5026.38 6183.59,5028.16 v1(6244.45,5028.16) ; v1(6370,5595) 6870,5095 v1(6870,4940) ; v1(6370,5685) 6395,5710 OLED_DISP.3
VCC_IN: D1.2 USB_IN.1 VCC_IN.1 VCC_IN.2 VCC_IN.3 VCC_IN.4 | length 1648.2
  Top Layer w13.8: USB_IN.1 3641.18,6381.19 v1(3695,6435)
  Bottom Layer w13.8: D1.2 3695,6148.39 v1(3695,6435) 3695,6895 VCC_IN.4 VCC_IN.3 VCC_IN.2 VCC_IN.1
VIN_PIN: C2.1 DOOR_CONTROL.2 ESP8266_CH340.1 ESP8266_NODEMCU.1 PWR.3 PWR_G.2 R10.1 VCC.1 VCC.2 VCC.3 VCC.4 VCC.5 VCC.6 VCC.7 VCC.8 VCC.9 VCC.10 | length 9353.2
  Top Layer w13.8: DOOR_CONTROL.2 5340,3435.36 ; VCC.10 VCC.9 VCC.8 VCC.7 VCC.6 VCC.5 VCC.4 VCC.3 VCC.2 VCC.1 5200,7025 4915,6740 4065,6740 3594.9,6269.9 3594.9,5585.92 PWR.3 3421.1,5412.12 C2.1 3450,4531.1 3450,4230.63 PWR_G.2 3609.37,4185.63 4359.64,3435.36 5340,3435.36 ; ESP8266_NODEMCU.1 ESP8266_CH340.1 6404.87,3519.87 5424.51,3519.87 5340,3435.36
  Bottom Layer w13.8: R10.1 PWR.3
VU_PIN: D1.1 PWR.2 VU.3 | length 4390.5
  Top Layer w13.8: v1(3339.35,5630) PWR.2 ; v1(5302.17,4289.11) 5416.01,4175.27 5850.27,4175.27 VU.3
  Bottom Layer w13.8: v1(3339.35,5630) 3339.35,5965.96 D1.1 ; PWR.2 3571.34,5751.34 3858.93,5751.34 4027.77,5582.5 4227.5,5582.5 4796.28,5013.72 4796.28,4794.99 v1(5302.17,4289.11)
WIFI_LED: R3.1 SHIFT_REG.5 U1.5 | length 3595.5
  Top Layer w13.8: v1(4890,5630) v1(5000,5630) ; v1(5490,5565) v1(5745,5565) ; v1(5935,5560) 6100,5395 U1.5 6180,5160 v1(6210,5160)
  Bottom Layer w13.8: R3.1 v1(4890,5630) ; v1(5000,5630) 5425,5630 v1(5490,5565) ; v1(5745,5565) 5930,5565 v1(5935,5560) ; v1(6210,5160) 6260,5160 6285,5135 6675,5135 6770,5040 6770,4870 SHIFT_REG.5
pads on no net: C2.2 DHT.1 DHT.2 DOOR_CONTROL.3 ESP8266_CH340.2 ESP8266_CH340.6 ESP8266_CH340.7 ESP8266_CH340.8 ESP8266_CH340.9 ESP8266_CH340.10 ESP8266_CH340.11 ESP8266_CH340.12 ESP8266_CH340.14 ESP8266_NODEMCU.2 ESP8266_NODEMCU.6 ESP8266_NODEMCU.7 ESP8266_NODEMCU.8 ESP8266_NODEMCU.9 ESP8266_NODEMCU.10 ESP8266_NODEMCU.11 ESP8266_NODEMCU.12 ESP8266_NODEMCU.14 ESP8266_NODEMCU.17 ESP8266_NODEMCU.24 ESP8266_NODEMCU.25 ESP8266_NODEMCU.27 GND.1 GND.2 GND.3 GND.4 GND.5 GND.6 GND.7 GND.8 GND.9 GND.10 GND_IN.1 GND_IN.2 GND_IN.3 GND_IN.4 IR_TRAN.3 LED1.1 LED2.1 LED3.1 LED4.1 LED_WIFI.1 MOTOR_CONTROL.2 MOTOR_CONTROL.3 MOTOR_CONTROL.6 MQ135.2 MQ135.3 OLED_DISP.4 R4.1 U1.8 U1.9 U1.13 USB_IN.4 USB_IN.5 USB_IN.6 USB_IN.7 USB_IN.8 USB_IN.9
copper on no net: | length 16941.8
  Top Layer w13.8: 3372.09,6470.74 3372.09,6434.93 ; 3488.23,6278.81 3372.45,6278.81 3372.09,6278.45 ; 3507.91,6189.26 3374.05,6189.26 3372.09,6191.22 3372.09,6278.45 ; 3507.91,6470.74 3507.91,6434.93 3420.89,6434.93 ; v1(3515.2,4423.46) 3558.9,4467.17 3558.9,4560 3815,4560 ; v1(3720,5915) 3720,5866.69 3721.69,5865 3721.69,5815.1 3815,5721.79 3815,5665 3815,5410 3815,5155 3815,4895 3815,4560 ; 4125,6925 4025,6925 3925,6925 3825,6925 3420.89,6520.89 3420.89,6434.93 ; 4600,6600 4694.41,6694.41 5210,6694.41 5210,6910 5225,6925 5325,6925 5425,6925 5525,6925 5625,6925 5725,6925 5825,6925 5925,6925 6025,6925 6125,6925 6125,6600 ; 5240,3855 5240.44,3854.56 5240.44,3755.74 ; 5740,4755 5830.78,4845.78 6200,4845.78 ; 6040,3655 6040,3755.74 ; 6040,3855 6040,3755.74 ; 6295,6600 6125,6600 ; 6440,3655 6440,3755.74 ; 6460,3385 6505,3340 6620,3340 6695,3415 6695,4086.49 6476.49,4305 6440,4305 ; 3372.09,6278.45 3372.09,6434.93 ; 3372.09,6434.93 3420.89,6434.93 ; 3815,4560 3920,4455 3920,4450 3975,4395 4165,4395 4220,4450 4320,4450 4320,4415 4979.26,3755.74 5240.44,3755.74 ; 5240.44,3755.74 6040,3755.74 ; 6040,3755.74 6440,3755.74 ; 6125,6600 5800,6275 5800,5240 5774.87,5214.87 5774.87,5150.99 5835.86,5090 6116.41,5090 6118.19,5091.78 6181.81,5091.78 6183.59,5090 6191.35,5090 6200,5081.35 6200,4940 6200,4845.78 ; 6200,4845.78 6349.22,4845.78 6440,4755 6440,4305 ; 6440,3755.74 6440,3855 6440,4305
  Bottom Layer w13.8: 3507.91,6189.26 3470,6151.35 3470,5915 v1(3720,5915) ; v1(3515.2,4423.46) 3515.2,4164.87 3638.29,4041.78 3650,4041.78 ; 5440,3385 5500,3325 6435,3325 6460,3350 6460,3385 ; 5510,6600 5525,6615 5525,6925

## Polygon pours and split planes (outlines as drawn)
no net on Top Layer (solid, remove dead copper): 3000,3000 7450,3000 7450,7450 3000,7450
no net on Bottom Layer (solid, remove dead copper, pour order 4): 3000,3011.43 7395,3011.43 7395,7425 3000,7425

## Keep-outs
Board Outline Layer:
  lines w10: 7222,6980.15 ccw(c7025.15,6980.15) 7025.15,7177 3481.85,7177 ccw(c3481.85,6980.15) 3285,6980.15 3285,3436.85 ccw(c3481.85,3436.85) 3481.85,3240 7025.15,3240 ccw(c7025.15,3436.85) 7222,3436.85 7222,6980.15 ; 7222,6980.15 7222,6980.15

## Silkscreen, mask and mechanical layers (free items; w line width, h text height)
Top Silkscreen Layer:
  lines w10: 3720,3318.9 4625.51,3318.9 4625.51,4500 3720,4500 3720,3318.9 ; 4157.4,5350.79 4944.8,5350.79 4944.8,6650 4157.4,6650 4157.4,5350.79 ; 5043.65,5232.68 5673.57,5232.68 5673.57,6650 5043.65,6650 5043.65,5232.68 ; 5755,5350.79 7132.95,5350.79 7132.95,6650 5755,6650 5755,5350.79
  text "5V" at 6330,6920 h117.97
  text "3.3V" at 4400,6910 h117.97
  text "POWER" at 3775.03,6748.9 h117.97
  text "SCL" at 6525,6525 h59.06 r90
  text "SDA" at 6629.53,6524.48 h59.06 r90
  text "VCC" at 5245,6515 h59.06 r90
  text "VCC" at 4735,6510 h59.06 r90
  text "IN" at 5345,6475 h59.06 r90
  text "IN" at 4430,6465 h59.06 r90
  text "GND" at 6317.03,6422.55 h59.06 r90
  text "VCC" at 6425,6420 h59.06 r90
  text "GND" at 5545,6415 h59.06 r90
  text "GND" at 4630,6410 h59.06 r90
  text "ESP8266 NodeMCU" at 4210,4955 h156.75
  text "Q1" at 6941.51,4868.86 h87.08
  text "Q2" at 6941.51,4768.86 h87.08
  text "Q3" at 6941.51,4668.86 h87.08
  text "Q4" at 6941.51,4568.86 h87.08
  text "GND" at 3955,4525 h59.06 r90
  text "M2" at 4050,4525 h59.06 r90
  text "VCC" at 4155,4525 h59.06 r90
  text "GND" at 4250,4525 h59.06 r90
  text "GND" at 4350,4525 h59.06 r90
  text "M1" at 4450,4525 h59.06 r90
  text "Q5" at 6941.51,4468.86 h87.08
  text "Q6" at 6941.51,4368.86 h87.08
  text "Q7" at 6941.51,4268.86 h87.08
  text "Q8" at 6941.51,4168.86 h87.08
  text "PWR" at 3350,4005 h104.5
  text "GND" at 5478.21,3467.37 h59.06 r90
  text "GND" at 6498.21,3467.37 h59.06 r90
  text "OUT" at 5278.22,3462.37 h59.06 r90
  text "VCC" at 5378.22,3462.37 h59.06 r90
  text "OUT" at 6298.22,3462.37 h59.06 r90
  text "VCC" at 6398.22,3462.37 h59.06 r90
